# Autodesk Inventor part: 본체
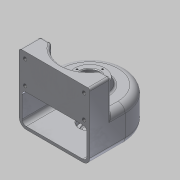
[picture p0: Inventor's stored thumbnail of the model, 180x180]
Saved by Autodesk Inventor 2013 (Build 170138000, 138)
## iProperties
Created: 2015-02
Part Number: 본체
Material: 알루미늄 6061
Document SubType Name: Modeling
Designer: Administrator
Density: 2.71 g/cm^3
Mass: 572.016 g
Surface Area: 705.488 cm^2
Volume: 211.076 cm^3
Author: Administrator
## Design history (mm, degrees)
sketch "스케치1"
  geometry: L1 (-50, 0)-(-50, -50); L2 (-50, -50)-(50, -50); L3 (50, -50)-(50, 0); A1 r 50 centre (0, 0) between (50, 0) and (-50, 0); 1 further point
  constraints: 6 end point, 2 coincident, 2 point on circle, 2 tangent, 1 centre point, 1 parallel, 1 perpendicular, 1 vertical
  dimensions: "d0" = 100 diameter of A1; "d2" = 50 distance from line of point (0, 0) L2
extrude "돌출1" new body sketch "스케치1" stored distance "d3" = 50; taper "d4" = 0 deg
fillet "모깎기1" dims "d5" = 10
feature "쉘1" dims "d6" = 4
sketch "스케치2"
  geometry: L1 (0, 25)-(40, 25) reference; L2 (0, 21)-(40, 21) reference; L3 (40, -21)-(0, -21) reference; L4 (40, -25)-(0, -25) reference; L5 (0, -25)-(-50, -25) reference; L6 (0, -21)-(-50, -21) reference; L7 (-50, 25)-(0, 25) reference; L8 (-50, 21)-(0, 21) reference; L9 (0, 25)-(0, -25); L10 (0, -25)-(20, -25); L11 (20, -25)-(20, -33); L12 (20, -33)-(0, -33); L13 (0, -33)-(0, -25); L14 (25, 25)-(21.36, 35); L15 (21.36, 35)-(0, 35); L16 (0, 35)-(0, 25); L17 (25, 25)-(0, 25); 1 further point
  constraints: 18 end point, 4 perpendicular, 2 parallel, 1 collinear, 1 horizontal, 1 point on line
  dimensions: "d7" = 40 diameter of L11 L9; "d9" = 8 distance of L10.end L11.end; "d10" = 50 diameter of L14.start L9; "d11" = 110 deg angle of L1 L14; "d12" = 10 distance between parallel lines of L1 L15
revolve "회전1" sketch "스케치2" stored, may be unused: angle "d13" = 90 deg
sketch "스케치3"
  geometry: L1 (40, -21)-(0, -21) reference; L2 (-20, -33)-(20, -33) reference; L3 (20, -25)-(-20, -25) reference; L4 (0, -21)-(-50, -21) reference; L5 (0, -33)-(0, -21); L6 (0, -21)-(14, -21); L7 (14, -21)-(14, -29); L8 (14, -29)-(10, -29); L9 (0, -29)-(0, -21); L10 (0, -31)-(8, -31); A1 r 2 centre (8, -29) between (8, -31) and (10, -29); 1 further point
  constraints: 12 end point, 3 perpendicular, 2 parallel, 2 point on circle, 2 point on line, 1 centre point, 1 horizontal, 1 midpoint, 1 tangent
  dimensions: "d14" = 28 diameter of L7 L5; "d16" = 8 distance of L6.end L7.end; "d17" = 2 distance between parallel lines of L8 L10; "d18" = 20 diameter of L8.end L5
revolve "회전2" sketch "스케치3" stored, may be unused: angle "d19" = 90 deg
hole "구멍1" diameter "d22" = 20; stored, may be unused: countersink angle "d26" = 90 deg, drill point angle "d28" = 0 deg; dims "d20" = 10, "d21" = 10, "d23" = 6, "d24" = 28, "d25" = 10, "d27" = 14
node "작업 평면1"
sketch "스케치4"
  geometry: L1 (-50, 0)-(-50, -50) reference; L2 (50, -50)-(50, 0) reference; L3 (-40, -50)-(40, -50) reference; L4 (-50, -20)-(-50, -50); L5 (-50, -50)-(50, -50); L6 (50, -50)-(50, -20); L7 (50, -20)-(34.641, -20); L8 (-50, -20)-(-34.641, -20); A1 r 40 centre (0, 0) between (-34.641, -20) and (34.641, -20); 1 further point
  constraints: 10 end point, 3 collinear, 2 point on circle, 2 point on line, 1 centre point, 1 coincident, 1 perpendicular
  dimensions: "d30" = 80 diameter of A1; "d31" = 30 distance between parallel lines of L5 L7
extrude "돌출2" join sketch "스케치4" stored distance "d32" = 50; taper "d33" = 0 deg
chamfer "모따기1" distance "d36" = 1; stored, may be unused: second distance "d37" = 2, angle "d38" = 45 deg
fillet "모깎기3" dims "d50" = 3, "d51" = 0.3
sketch "스케치6"
  geometry: C1 r 21.36 at (0, 0) reference; 1 further point
  constraints: 1 vertical alignment
  dimensions: "d52" = 18 distance of C1.centre point (0, 18)
hole "구멍3" sketch "스케치6" at (0, 18) diameter "d53" = 2.459; stored, may be unused: countersink angle "d57" = 90 deg, drill point angle "d59" = 118 deg; dims "d54" = 6, "d55" = 28, "d56" = 10, "d58" = 9
node "작업 평면2"
sketch "스케치7"
  geometry: L1 (40, -25)-(-40, -25) reference; 2 further points
  constraints: 1 coincident, 1 other
  dimensions: "d64" = 25 distance from line of L1 point (0, 0)
feature "엠보싱1" sketch "스케치7" dims "d0" = 100, "d2" = 50, "d65" = 0.5, "d66" = 0
sketch "스케치8"
  geometry: L1 (-7, 95)-(87, 95) reference; L2 (80, 0)-(0, 0) reference; L3 (40, 95)-(40, 0); 5 further points
  constraints: 2 end point, 2 horizontal alignment, 2 midpoint, 2 vertical alignment, 1 symmetric about line
  dimensions: "d68" = 33 distance of point (81.75, 86) point (81.75, 53); "d70" = 9 distance from line of L1 point (81.75, 86); "d71" = 83.5 distance of point (-1.75, 86) point (81.75, 86)
hole "구멍4" sketch "스케치8" at (-1.75, 86), (81.75, 86), (81.75, 53), (-1.75, 53) diameter "d72" = 5.134; stored, may be unused: countersink angle "d76" = 90 deg, drill point angle "d78" = 118 deg; dims "d73" = 10, "d74" = 28, "d75" = 10, "d77" = 13
node "솔리드1"
pattern_circular "원형 패턴2" dims angle "d61" = 360 deg
node "투영된 루프1"
other parameters: "d29" = -95
